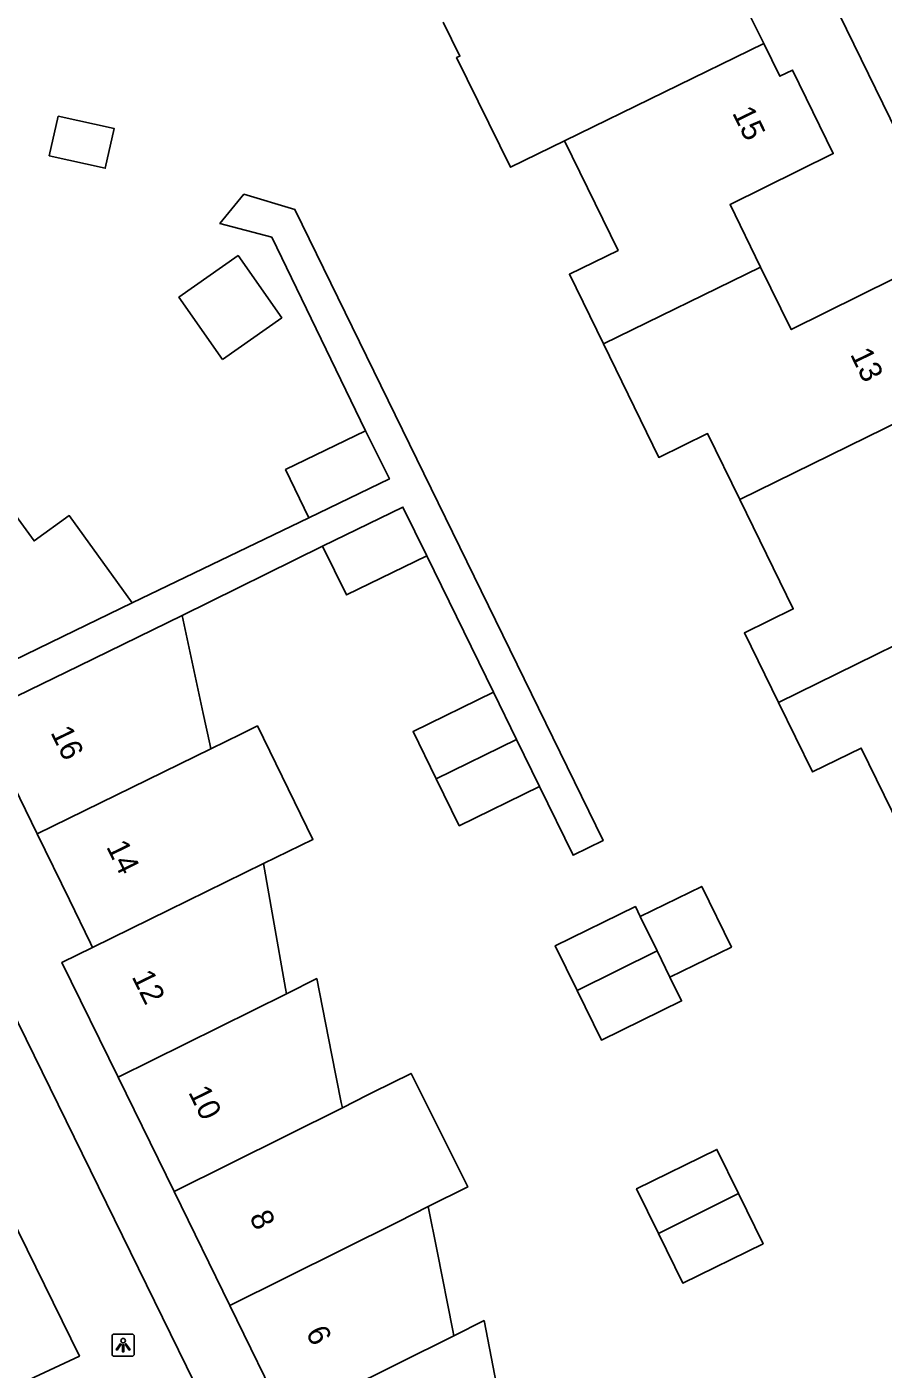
# Model space of a CAD drawing. Extents: x 160457 to 162082, y 388340 to 389736.
# Drawn here: x 160788.7 to 160827.1, y 388927.4 to 388987.6 of the extents above; entities that cross this region are included whole.
import ezdxf

# ---------------------------------------------------------------- set-up
doc = ezdxf.new("R2010")
doc.units = 0
for name, color, linetype in [('IMGEO_Lichtpunt', 7, 'Continuous'), ('IMGEO_Pand', 7, 'Continuous'), ('IMGEO_Pand_nummerreeks', 7, 'Continuous'), ('IMGEO_Voetpad_open', 7, 'Continuous')]:
    doc.layers.add(name, color=color, linetype=linetype)

msp = doc.modelspace()

# ---------------------------------------------------------------- linework, layer by layer
at = {"layer": 'IMGEO_Lichtpunt'}
for p, q in [((160793.384, 388928.957), (160792.576, 388928.957)), ((160793.384, 388928.957), (160792.576, 388928.957)), ((160792.482, 388928.862), (160792.482, 388928.055)), ((160792.482, 388928.862), (160792.482, 388928.055)), ((160793.478, 388928.055), (160793.478, 388928.862)), ((160793.478, 388928.055), (160793.478, 388928.862)), ((160792.576, 388927.961), (160793.384, 388927.961)), ((160792.576, 388927.961), (160793.384, 388927.961))]:
    msp.add_line(p, q, dxfattribs=at)
for points in [[(160792.856, 388928.526), (160792.895, 388928.498), (160792.707, 388928.236), (160792.669, 388928.263), (160792.856, 388928.526)], [(160792.958, 388928.478), (160793.005, 388928.478), (160793.005, 388928.156), (160792.958, 388928.156), (160792.958, 388928.478)], [(160793.068, 388928.498), (160793.106, 388928.525), (160793.293, 388928.263), (160793.254, 388928.235), (160793.068, 388928.498)]]:
    msp.add_lwpolyline(points, dxfattribs=at)
msp.add_circle((160792.981, 388928.66), 0.0994, dxfattribs=at)
for centre, start, end in [((160792.576, 388928.862), 90, 180), ((160792.576, 388928.862), 90, 180), ((160793.384, 388928.862), 0, 90), ((160793.384, 388928.862), 0, 90), ((160792.576, 388928.055), 180, 270), ((160792.576, 388928.055), 180, 270), ((160793.384, 388928.055), 270, 0), ((160793.384, 388928.055), 270, 360)]:
    msp.add_arc(centre, 0.0946, start, end, dxfattribs=at)
at = {"layer": 'IMGEO_Pand'}
for points in [[(160812.281, 388994.076), (160813.426, 388993.174), (160813.938, 388993.424), (160815.475, 388990.279), (160819.73, 388992.368), (160821.557, 388988.625), (160820.99, 388988.349), (160821.732, 388986.849)], [(160812.793, 388982.487), (160810.372, 388981.306), (160807.944, 388986.221), (160808.094, 388986.294), (160807.341, 388987.818)], [(160821.732, 388986.849), (160812.793, 388982.487)], [(160821.59, 388976.823), (160820.218, 388979.629), (160824.847, 388981.913), (160823.021, 388985.661), (160822.455, 388985.385), (160821.732, 388986.849)], [(160790.061, 388983.602), (160789.664, 388981.817), (160792.181, 388981.258), (160792.578, 388983.043), (160790.061, 388983.602)], [(160812.793, 388982.487), (160815.196, 388977.569), (160813.006, 388976.499), (160814.532, 388973.375)], [(160797.446, 388972.685), (160800.099, 388974.552), (160798.139, 388977.339), (160795.485, 388975.472), (160797.446, 388972.685)], [(160814.532, 388973.375), (160821.59, 388976.823)], [(160821.59, 388976.823), (160822.963, 388974.017), (160827.586, 388976.311), (160829.424, 388972.56), (160828.859, 388972.283), (160829.591, 388970.781)], [(160820.652, 388966.404), (160819.209, 388969.356), (160817.019, 388968.286), (160814.532, 388973.375)], [(160829.591, 388970.781), (160820.652, 388966.404)], [(160801.322, 388965.571), (160800.269, 388967.738), (160803.864, 388969.485)], [(160803.864, 388969.485), (160804.929, 388967.323), (160801.322, 388965.571)], [(160793.391, 388961.76), (160790.566, 388965.678), (160788.985, 388964.537), (160788.269, 388965.524), (160787.053, 388967.2), (160786.902, 388967.409)], [(160822.391, 388957.291), (160820.865, 388960.415), (160823.055, 388961.485), (160820.652, 388966.404)], [(160801.935, 388964.298), (160805.537, 388966.059), (160806.604, 388963.877)], [(160806.604, 388963.877), (160803.001, 388962.116), (160801.935, 388964.298)], [(160785.772, 388958.073), (160790.273, 388960.251), (160793.391, 388961.76)], [(160832.006, 388962.013), (160822.391, 388957.291)], [(160795.635, 388961.199), (160791.006, 388958.94), (160786.512, 388956.747)], [(160796.915, 388955.213), (160796.867, 388955.436), (160796.577, 388956.793), (160795.635, 388961.199)], [(160807.035, 388953.865), (160805.996, 388955.99), (160809.599, 388957.752)], [(160809.599, 388957.752), (160810.636, 388955.631)], [(160828.51, 388950.32), (160826.103, 388955.247), (160823.913, 388954.177), (160822.391, 388957.291)], [(160786.512, 388956.747), (160789.121, 388951.402)], [(160799.284, 388950.064), (160801.5, 388951.151), (160799.006, 388956.236), (160798.263, 388955.872), (160796.915, 388955.213)], [(160807.035, 388953.865), (160810.636, 388955.631)], [(160810.636, 388955.631), (160811.667, 388953.521)], [(160789.121, 388951.402), (160796.915, 388955.213)], [(160811.667, 388953.521), (160808.064, 388951.76), (160807.035, 388953.865)], [(160789.121, 388951.402), (160790.571, 388948.432), (160791.519, 388946.489), (160791.611, 388946.301)], [(160791.611, 388946.301), (160799.284, 388950.064)], [(160800.311, 388944.226), (160800.269, 388944.463), (160799.718, 388947.594), (160799.284, 388950.064)], [(160817.519, 388944.969), (160820.278, 388946.317), (160818.946, 388949.041), (160816.187, 388947.692)], [(160816.187, 388947.692), (160815.97, 388948.136), (160812.376, 388946.379), (160813.361, 388944.365)], [(160816.187, 388947.692), (160816.942, 388946.149)], [(160791.611, 388946.301), (160790.236, 388945.627), (160792.756, 388940.475)], [(160813.361, 388944.365), (160816.942, 388946.149)], [(160816.942, 388946.149), (160817.519, 388944.969)], [(160802.818, 388939.112), (160802.771, 388939.349), (160802.335, 388941.549), (160801.67, 388944.901), (160800.311, 388944.226)], [(160813.361, 388944.365), (160814.445, 388942.148), (160818.039, 388943.904), (160817.519, 388944.969)], [(160800.311, 388944.226), (160792.756, 388940.475)], [(160792.756, 388940.475), (160795.264, 388935.349)], [(160806.674, 388934.673), (160808.443, 388935.555), (160805.904, 388940.65), (160804.172, 388939.787), (160803.936, 388939.67), (160802.818, 388939.112)], [(160802.818, 388939.112), (160795.264, 388935.349)], [(160817.009, 388933.467), (160816.026, 388935.476), (160819.629, 388937.237), (160820.597, 388935.257)], [(160795.264, 388935.349), (160797.767, 388930.233)], [(160817.009, 388933.467), (160820.597, 388935.257)], [(160820.597, 388935.257), (160821.697, 388933.007), (160818.095, 388931.246), (160817.009, 388933.467)], [(160797.767, 388930.233), (160805.32, 388933.998), (160806.674, 388934.673)], [(160807.822, 388928.883), (160807.775, 388929.121), (160807.07, 388932.677), (160806.674, 388934.673)], [(160797.767, 388930.233), (160800.271, 388925.116)], [(160810.325, 388923.767), (160810.277, 388924.007), (160809.666, 388927.089), (160809.176, 388929.559), (160807.822, 388928.883)], [(160807.822, 388928.883), (160800.271, 388925.116)]]:
    msp.add_lwpolyline(points, dxfattribs=at)
at = {"layer": 'IMGEO_Voetpad_open'}
for points in [[(160819.315, 389000), (160825.449, 388987.505), (160869.221, 388897.954)], [(160803.864, 388969.485), (160799.648, 388978.161), (160797.321, 388978.786), (160798.401, 388980.092), (160800.689, 388979.406), (160814.522, 388951.096), (160813.174, 388950.437), (160811.667, 388953.521)], [(160793.391, 388961.76), (160801.322, 388965.571)], [(160801.935, 388964.298), (160795.635, 388961.199)], [(160809.599, 388957.752), (160806.604, 388963.877)], [(160803.386, 388912.082), (160787.173, 388945.121)], [(160783.12, 388935.047), (160786.705, 388936.744), (160791.019, 388927.969), (160786.936, 388926.069)]]:
    msp.add_lwpolyline(points, dxfattribs=at)

# ---------------------------------------------------------------- texts
at = {"layer": 'IMGEO_Pand_nummerreeks'}
for s, rotation, p in [('15', 296.07855, (160820.298, 388983.745)), ('13', 295.91294, (160825.59, 388972.915)), ('16', 296.0178, (160789.705, 388955.95)), ('14', 296.0178, (160792.208, 388950.821)), ('12', 296.06937, (160793.351, 388944.995)), ('10', 296.06937, (160795.89, 388939.807)), ('8', 296.06937, (160798.627, 388934.21)), ('6', 296.06937, (160801.16, 388929.031))]:
    msp.add_text(s, height=1, rotation=rotation, dxfattribs=at).set_placement(p)

doc.saveas('drawing.dxf')
